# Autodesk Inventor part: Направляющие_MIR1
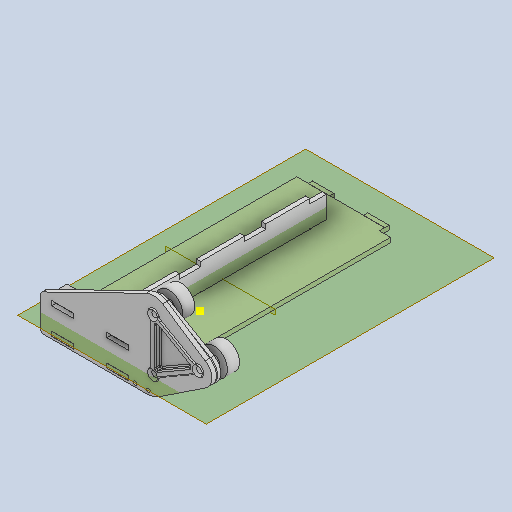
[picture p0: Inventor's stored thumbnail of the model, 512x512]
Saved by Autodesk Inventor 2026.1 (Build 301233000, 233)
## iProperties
Created: 2025-12
Part Number: Направляющие_MIR1
Material: Типовые
Document SubType Name: Modeling
Designer: Yury Melnikov
Density: 1 g/cm^3
Appearance: По умолчанию
Author: Yury Melnikov
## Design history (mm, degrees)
derived "Направляющие.ipt"
  sketch "Эскиз1"
    geometry: L1 (0, 0)-(-16, 0) reference; L2 (-16, 0)-(-16, -200) reference; L3 (-16, -200)-(0, -200) reference; L4 (0, -200)-(0, 0) reference; 1 further point
  sketch "Эскиз2"
    geometry: 1 further point
  sketch "Эскиз3"
    geometry: L1 (0, 0)-(0, -200) reference; L2 (16, -200)-(16, 0) reference; L3 (28.3, -33.725)-(-12.3, -10.284) reference; L4 (-12.3, -10.284)-(-12.3, -57.165) reference; L5 (-12.3, -57.165)-(28.3, -33.725) reference; C1 r 12.3 at (28.3, -33.725) reference; C2 r 12.3 at (-12.3, -10.284) reference; C3 r 12.3 at (-12.3, -57.165) reference; 1 further point
    constraints: 1 other
  sketch "Эскиз4"
    geometry: C1 r 12.3 at (0, 0) reference; C2 r 12.3 at (-40.6, 23.44) reference; C3 r 12.3 at (-40.6, -23.44) reference; C4 r 4 at (0, 0) reference; C5 r 4 at (-40.6, 23.44) reference; C6 r 4 at (-40.6, -23.44) reference; 1 further point
  sketch "Эскиз5"
    geometry: L1 (6.15, 10.652)-(-34.45, 34.093) reference; L2 (-52.9, 23.44)-(-52.9, -23.44) reference; L3 (-34.45, -34.093)-(6.15, -10.652) reference; A1 r 12.3 centre (-40.6, -23.44) between (-34.45, -34.093) and (-52.9, -23.44) reference; A2 r 12.3 centre (-40.6, 23.44) between (-52.9, 23.44) and (-34.45, 34.093) reference; A3 r 12.3 centre (0, 0) between (6.15, -10.652) and (6.15, 10.652) reference; 1 further point
  sketch "Эскиз6"
    geometry: L1 (0, 0)-(-40.6, 23.44) reference; L2 (-40.6, 23.44)-(-40.6, -23.44) reference; L3 (-40.6, -23.44)-(0, 0) reference; L4 (-35.6, 23.44)-(-2.5, 4.33) reference; L5 (-2.5, -4.33)-(-35.6, -23.44) reference; L6 (-43.1, -19.11)-(-43.1, 19.11) reference; L7 (-38.1, 19.11)-(-5, 0) reference; L8 (-5, 0)-(-38.1, -19.11) reference; L9 (-38.1, -19.11)-(-38.1, 19.11) reference; C1 r 12.3 at (-40.6, 23.44) reference; C2 r 12.3 at (-40.6, -23.44) reference; C3 r 12.3 at (0, 0) reference; C4 r 2.5 at (0, 0) reference; C5 r 2.5 at (-40.6, 23.44) reference; C6 r 2.5 at (-40.6, -23.44) reference; A1 r 5 centre (-40.6, 23.44) between (-35.6, 23.44) and (-43.1, 19.11) reference; A2 r 5 centre (0, 0) between (-2.5, -4.33) and (-2.5, 4.33) reference; A3 r 5 centre (-40.6, -23.44) between (-43.1, -19.11) and (-35.6, -23.44) reference; 3 further points
    constraints: 2 other
  sketch "Эскиз7"
    geometry: C1 r 2.5 at (-40.6, 23.44) reference; C2 r 2.5 at (0, 0) reference; C3 r 2.5 at (-40.6, -23.44) reference; 1 further point
  sketch "Эскиз8"
    geometry: L1 (-4.478, 5.472)-(-33.622, 22.298) reference; L2 (-43.1, 16.826)-(-43.1, -16.826) reference; L3 (-33.622, -22.298)-(-4.478, -5.472) reference; L4 (-34.45, 34.093)-(6.15, 10.652) reference; L5 (6.15, -10.652)-(-34.45, -34.093) reference; L6 (-52.9, -23.44)-(-52.9, 23.44) reference; L7 (-30, -82.992)-(-34, -82.992) reference; L8 (-28.3, 33.725)-(-28.3, -166.275) reference; L9 (-142.9, -11.74)-(-142.9, -38.74) reference; L10 (-139.9, -41.74)-(-46.638, -41.74) reference; L11 (-35.571, -38.399)-(6.806, -10.245) reference; L12 (-34.45, 34.093)-(6.15, 10.652) reference; L13 (6.15, 10.652)-(-32.359, 35.974) reference; L14 (-141.217, -9.045)-(-47.187, 36.917) reference; A1 r 5 centre (-1.978, -9.802) between (-0.989, -4.901) and (-4.478, -5.472) reference; A2 r 5 centre (0, 0) between (-0.989, -4.901) and (-0.989, 4.901) reference; A3 r 5 centre (-1.978, 9.802) between (-4.478, 5.472) and (-0.989, 4.901) reference; A4 r 5 centre (-31.122, 26.628) between (-35.861, 25.034) and (-33.622, 22.298) reference; A5 r 5 centre (-40.6, 23.44) between (-35.861, 25.034) and (-44.35, 20.133) reference; A6 r 5 centre (-48.1, 16.826) between (-43.1, 16.826) and (-44.35, 20.133) reference; A7 r 5 centre (-48.1, -16.826) between (-44.35, -20.133) and (-43.1, -16.826) reference; A8 r 5 centre (-40.6, -23.44) between (-44.35, -20.133) and (-35.861, -25.034) reference; A9 r 5 centre (-31.122, -26.628) between (-33.622, -22.298) and (-35.861, -25.034) reference; A10 r 12.3 centre (-40.6, 23.44) between (-34.45, 34.093) and (-52.9, 23.44) reference; A11 r 12.3 centre (0, 0) between (6.15, -10.652) and (6.15, 10.652) reference; A12 r 12.3 centre (-40.6, -23.44) between (-52.9, -23.44) and (-34.45, -34.093) reference; A13 r 12.3 centre (0, 0) between (6.15, -10.652) and (6.15, 10.652) reference; A14 r 12.3 centre (-40.6, 23.44) between (-34.45, 34.093) and (-52.9, 23.44) reference; A15 r 20 centre (-46.638, -21.74) between (-46.638, -41.74) and (-35.571, -38.399) reference; A16 r 3 centre (-139.9, -11.74) between (-141.217, -9.045) and (-142.9, -11.74) reference; A17 r 3 centre (-139.9, -38.74) between (-142.9, -38.74) and (-139.9, -41.74) reference; A18 r 15 centre (-40.6, 23.44) between (-28.3, 14.855) and (-26.541, 18.21) reference; A19 r 15 centre (-40.6, 23.44) between (-32.359, 35.974) and (-47.187, 36.917) reference; 5 further points
  sketch "Эскиз17"
    geometry: L1 (-15.8, 7.674)-(-15.8, 4.326) reference; L2 (-15.8, 4.326)-(-12.9, 2.651) reference; L3 (-12.9, 2.651)-(-10, 4.326) reference; L4 (-10, 4.326)-(-10, 7.674) reference; L5 (-10, 7.674)-(-12.9, 9.349) reference; L6 (-12.9, 9.349)-(-15.8, 7.674) reference; L7 (-12.9, 0.342)-(-17.8, 3.171) reference; L8 (-17.8, 3.171)-(-17.8, 8.829) reference; L9 (-17.8, 8.829)-(-12.9, 11.658) reference; L10 (-12.9, 11.658)-(-8, 8.829) reference; L11 (-8, 8.829)-(-8, 3.171) reference; L12 (-8, 3.171)-(-12.9, 0.342) reference; L13 (0, 0)-(0, 12) reference; L14 (0, 17)-(-89.98, 17) reference; L15 (-29.393, 8.829)-(-29.393, 3.171) reference; L16 (-31.393, 4.326)-(-31.393, 7.674) reference; L17 (-34.293, 2.651)-(-31.393, 4.326) reference; L18 (-34.293, 11.658)-(-29.393, 8.829) reference; L19 (-29.393, 3.171)-(-34.293, 0.342) reference; L20 (-31.393, 7.674)-(-34.293, 9.349) reference; L21 (-37.193, 4.326)-(-34.293, 2.651) reference; L22 (-37.193, 7.674)-(-37.193, 4.326) reference; L23 (-34.293, 9.349)-(-37.193, 7.674) reference; L24 (-34.293, 0.342)-(-39.193, 3.171) reference; L25 (-39.193, 3.171)-(-39.193, 8.829) reference; L26 (-39.193, 8.829)-(-34.293, 11.658) reference; L27 (-50.786, 8.829)-(-50.786, 3.171) reference; L28 (-52.786, 4.326)-(-52.786, 7.674) reference; L29 (-55.686, 2.651)-(-52.786, 4.326) reference; L30 (-55.686, 11.658)-(-50.786, 8.829) reference; L31 (-50.786, 3.171)-(-55.686, 0.342) reference; L32 (-52.786, 7.674)-(-55.686, 9.349) reference; L33 (-58.586, 4.326)-(-55.686, 2.651) reference; L34 (-58.586, 7.674)-(-58.586, 4.326) reference; L35 (-55.686, 9.349)-(-58.586, 7.674) reference; L36 (-55.686, 0.342)-(-60.586, 3.171) reference; L37 (-60.586, 3.171)-(-60.586, 8.829) reference; L38 (-60.586, 8.829)-(-55.686, 11.658) reference; L39 (-72.18, 8.829)-(-72.18, 3.171) reference; L40 (-74.18, 4.326)-(-74.18, 7.674) reference; L41 (-77.08, 2.651)-(-74.18, 4.326) reference; L42 (-77.08, 11.658)-(-72.18, 8.829) reference; L43 (-72.18, 3.171)-(-77.08, 0.342) reference; L44 (-74.18, 7.674)-(-77.08, 9.349) reference; L45 (-79.98, 4.326)-(-77.08, 2.651) reference; L46 (-79.98, 7.674)-(-79.98, 4.326) reference; L47 (-77.08, 9.349)-(-79.98, 7.674) reference; L48 (-77.08, 0.342)-(-81.98, 3.171) reference; L49 (-81.98, 3.171)-(-81.98, 8.829) reference; L50 (-81.98, 8.829)-(-77.08, 11.658) reference; L51 (-89.98, 0)-(-89.98, 12) reference; 11 further points
    constraints: 1 horizontal, 1 other
  sketch "Эскиз18"
    geometry: L1 (-5.8, 3.349)-(-2.9, 5.023) reference; L2 (-2.9, 5.023)-(0, 3.349) reference; L3 (0, 3.349)-(0, 0) reference; L4 (0, 0)-(-2.9, -1.674) reference; L5 (-2.9, -1.674)-(-5.8, 0) reference; L6 (-5.8, 0)-(-5.8, 3.349) reference; L7 (-5.8, 3.349)-(-5.8, 0) reference; L8 (10, 7.674)-(-79.98, 7.674) reference; C1 r 1.65 at (-2.9, 1.674) reference; C2 r 1.65 at (-24.293, 1.674) reference; C3 r 1.65 at (-45.686, 1.674) reference; C4 r 1.65 at (-67.08, 1.674) reference; 3 further points
    constraints: 1 horizontal
  sketch "Эскиз19"
    geometry: L1 (82.72, -35.74)-(82.72, -39.54) reference; L2 (63.12, -35.74)-(82.72, -35.74) reference; L3 (63.12, -39.54)-(63.12, -35.74) reference; L4 (82.72, -39.54)-(63.12, -39.54) reference; L5 (62.92, -11.54)-(82.92, -11.54) reference; L6 (82.92, -11.54)-(82.92, -15.74) reference; L7 (82.92, -15.74)-(62.92, -15.74) reference; L8 (62.92, -15.74)-(62.92, -11.54) reference; L9 (142.9, -15.74)-(52.92, -15.74) reference; L10 (112.9, -11.54)-(132.9, -11.54) reference; L11 (132.9, -11.54)-(132.9, -15.74) reference; L12 (132.9, -15.74)-(112.9, -15.74) reference; L13 (112.9, -15.74)-(112.9, -11.54) reference; L14 (112.9, -39.74)-(112.9, -35.54) reference; L15 (132.9, -35.54)-(132.9, -39.74) reference; L16 (62.92, -39.74)-(62.92, -35.54) reference; L17 (82.92, -35.54)-(82.92, -39.74) reference; 1 further point
  sketch "Эскиз20"
    geometry: L1 (-47.09, -35)-(-42.89, -35) reference; L2 (-42.89, -35)-(-42.89, -75) reference; L3 (-42.89, -75)-(-47.09, -75) reference; L4 (-47.09, -75)-(-47.09, -35) reference; L5 (-47.09, -94)-(-42.89, -94) reference; L6 (-42.89, -94)-(-42.89, -134) reference; L7 (-42.89, -134)-(-47.09, -134) reference; L8 (-47.09, -134)-(-47.09, -94) reference; L9 (-47.09, -153)-(-42.89, -153) reference; L10 (-42.89, -153)-(-42.89, -193) reference; L11 (-42.89, -193)-(-47.09, -193) reference; L12 (-47.09, -193)-(-47.09, -153) reference; L13 (0, -20)-(-89.98, -20) reference; L14 (0, 0)-(-89.98, 0) reference; L15 (-89.98, -228)-(0, -228) reference; 3 further points
    constraints: 1 vertical
  sketch "Эскиз21"
    geometry: L1 (-47.09, -193)-(-42.89, -193) reference; L2 (-42.89, -193)-(-42.89, -153) reference; L3 (-42.89, -153)-(-47.09, -153) reference; L4 (-47.09, -153)-(-47.09, -193) reference; L5 (-47.09, -134)-(-42.89, -134) reference; L6 (-42.89, -134)-(-42.89, -94) reference; L7 (-42.89, -94)-(-47.09, -94) reference; L8 (-47.09, -94)-(-47.09, -134) reference; L9 (-47.09, -75)-(-42.89, -75) reference; L10 (-42.89, -75)-(-42.89, -35) reference; L11 (-42.89, -35)-(-47.09, -35) reference; L12 (-47.09, -35)-(-47.09, -75) reference; L13 (-89.98, 0)-(0, 0) reference; L14 (0, 0)-(0, -228) reference; L15 (-89.98, -228)-(0, -228) reference; L16 (-89.98, 0)-(-89.98, -228) reference; L17 (-46.99, -74.9)-(-42.99, -74.9) reference; L18 (-42.99, -74.9)-(-42.99, -35.1) reference; L19 (-42.99, -35.1)-(-46.99, -35.1) reference; L20 (-46.99, -35.1)-(-46.99, -74.9) reference; L21 (-46.99, -133.9)-(-42.99, -133.9) reference; L22 (-42.99, -133.9)-(-42.99, -94.1) reference; L23 (-42.99, -94.1)-(-46.99, -94.1) reference; L24 (-46.99, -94.1)-(-46.99, -133.9) reference; L25 (-46.99, -192.9)-(-42.99, -192.9) reference; L26 (-42.99, -192.9)-(-42.99, -153.1) reference; L27 (-42.99, -153.1)-(-46.99, -153.1) reference; L28 (-46.99, -153.1)-(-46.99, -192.9) reference; L29 (0, -20)-(-89.98, -20) reference; L30 (-46.99, -20)-(-42.99, -20) reference; L31 (-42.99, -20)-(-42.99, -208) reference; L32 (-42.99, -208)-(-46.99, -208) reference; L33 (-46.99, -208)-(-46.99, -20) reference; C1 r 1.65 at (-55.686, -14) reference; C2 r 1.65 at (-34.293, -14) reference; C3 r 1.65 at (-77.08, -14) reference; C4 r 1.65 at (-12.9, -14) reference; 1 further point
  sketch "Эскиз22"
    geometry: L1 (-46.99, -20)-(-42.99, -20) reference; L2 (-42.99, -20)-(-42.99, -208) reference; L3 (-42.99, -208)-(-46.99, -208) reference; L4 (-46.99, -208)-(-46.99, -20) reference; L5 (0, -20)-(-89.98, -20) reference; L6 (-89.98, -228)-(0, -228) reference; 3 further points
  node "РабПлоскость1"
  node "РабПлоскость2"
  node "РабПлоскость3"
  node "РабПлоскость4"
feature "Твердое тело1::Направляющие.ipt" dims "d0" = 10
feature "Твердое тело2::Направляющие.ipt" dims "d0" = 10
feature "Каретка::Направляющие.ipt" dims "d0" = 10
feature "Рука::Направляющие.ipt" dims "d0" = 10
feature "Основная плита::Направляющие.ipt" dims "d0" = 10
feature "Крепление::Направляющие.ipt" dims "d0" = 10
feature "Ребро жесткости::Направляющие.ipt" dims "d0" = 10
tag "Элемент создания тегов1"
sketch "Эскиз11"
  geometry: L1 (6.806, -10.245)-(-35.571, -38.399) reference; L2 (-46.638, -41.74)-(-139.9, -41.74) reference; L3 (-142.9, -38.74)-(-142.9, -11.74) reference; L4 (-33.622, -22.298)-(-4.478, -5.472) reference; L5 (-4.478, 5.472)-(-33.622, 22.298) reference; L6 (-43.1, 16.826)-(-43.1, -16.826) reference; L7 (-31.268, -35.54)-(-142.9, -35.54) reference; L8 (-37.92, -39.74)-(-142.728, -39.74) reference; L9 (-62.92, -35.54)-(-82.92, -35.54) reference; L10 (-82.92, -35.54)-(-82.92, -39.74) reference; L11 (-82.92, -39.74)-(-62.92, -39.74) reference; L12 (-62.92, -39.74)-(-62.92, -35.54) reference; L13 (-112.9, -35.54)-(-132.9, -35.54) reference; L14 (-132.9, -35.54)-(-132.9, -39.74) reference; L15 (-132.9, -39.74)-(-112.9, -39.74) reference; L16 (-112.9, -39.74)-(-112.9, -35.54) reference; L17 (-32.359, 35.974)-(6.15, 10.652) reference; L18 (-141.217, -9.045)-(-47.187, 36.917) reference; A1 r 12.3 centre (0, 0) between (6.806, -10.245) and (6.15, 10.652) reference; A2 r 20 centre (-46.638, -21.74) between (-46.638, -41.74) and (-35.571, -38.399) reference; A3 r 3 centre (-139.9, -38.74) between (-142.9, -38.74) and (-139.9, -41.74) reference; A4 r 3 centre (-139.9, -11.74) between (-141.217, -9.045) and (-142.9, -11.74) reference; A5 r 5 centre (-1.978, -9.802) between (-0.989, -4.901) and (-4.478, -5.472) reference; A6 r 5 centre (0, 0) between (-0.989, -4.901) and (-0.989, 4.901) reference; A7 r 5 centre (-1.978, 9.802) between (-4.478, 5.472) and (-0.989, 4.901) reference; A8 r 5 centre (-31.122, 26.628) between (-35.861, 25.034) and (-33.622, 22.298) reference; A9 r 5 centre (-40.6, 23.44) between (-35.861, 25.034) and (-44.35, 20.133) reference; A10 r 5 centre (-48.1, 16.826) between (-43.1, 16.826) and (-44.35, 20.133) reference; A11 r 5 centre (-48.1, -16.826) between (-44.35, -20.133) and (-43.1, -16.826) reference; A12 r 5 centre (-40.6, -23.44) between (-44.35, -20.133) and (-35.861, -25.034) reference; A13 r 5 centre (-31.122, -26.628) between (-33.622, -22.298) and (-35.861, -25.034) reference; A14 r 15 centre (-40.6, 23.44) between (-32.359, 35.974) and (-47.187, 36.917) reference; 1 further point
sketch "Эскиз14"
  geometry: L1 (142.9, -35.54)-(52.92, -35.54) reference; L2 (52.92, -35.54)-(52.92, -39.74) reference; L3 (52.92, -39.74)-(142.9, -39.74) reference; L4 (142.9, -39.74)-(142.9, -35.54) reference; L5 (82.92, -35.54)-(62.92, -35.54) reference; L6 (62.92, -39.74)-(82.92, -39.74) reference; L7 (62.92, -35.54)-(62.92, -39.74) reference; L8 (142.9, -38.74)-(142.9, -11.74) reference; 2 further points
sketch "Эскиз15"
  geometry: L1 (-3, 15)-(-3, 11.2) reference; L2 (-3, 11.2)-(-8, 6.2) reference; L3 (-8, 6.2)-(-20, 6.2) reference; L4 (-20, 6.2)-(-20, 3.2) reference; L5 (-20, 3.2)-(0, 3.2) reference; L6 (0, 3.2)-(-228, 3.2) reference; L7 (0, 3.2)-(0, 23) reference; L8 (0, 23)-(-20, 23) reference; L9 (-3, 15)-(-8, 20) reference; L10 (-8, 20)-(-20, 20) reference; L11 (-20, 20)-(-20, 23) reference; 5 further points; 1 other entity
  constraints: 1 other
sketch "Эскиз16"
  geometry: L1 (-52.92, -35.54)-(-142.9, -35.54) reference; L2 (-52.92, -39.74)-(-52.92, -35.54) reference; L3 (-142.9, -39.74)-(-52.92, -39.74) reference; L4 (-142.9, -35.54)-(-142.9, -39.74) reference; L5 (-132.9, -35.54)-(-132.9, -39.74) reference; L6 (-132.9, -39.74)-(-112.9, -39.74) reference; L7 (-112.9, -39.74)-(-112.9, -35.54) reference; L8 (-112.9, -35.54)-(-132.9, -35.54) reference; L9 (-82.92, -35.54)-(-82.92, -39.74) reference; L10 (-82.92, -39.74)-(-62.92, -39.74) reference; L11 (-62.92, -39.74)-(-62.92, -35.54) reference; L12 (-62.92, -35.54)-(-82.92, -35.54) reference; L13 (6.806, -10.245)-(-35.571, -38.399) reference; L14 (-46.638, -41.74)-(-139.9, -41.74) reference; L15 (-142.9, -38.74)-(-142.9, -11.74) reference; L16 (-141.217, -9.045)-(-47.187, 36.917) reference; L17 (-32.359, 35.974)-(6.15, 10.652) reference; L18 (-33.622, -22.298)-(-4.478, -5.472) reference; L19 (-4.478, 5.472)-(-33.622, 22.298) reference; L20 (-43.1, 16.826)-(-43.1, -16.826) reference; L21 (-82.72, -39.54)-(-82.72, -35.74) reference; L22 (-82.72, -35.74)-(-63.12, -35.74) reference; L23 (-63.12, -35.74)-(-63.12, -39.54) reference; L24 (-63.12, -39.54)-(-82.72, -39.54) reference; L25 (-113.1, -35.74)-(-113.1, -39.54) reference; L26 (-113.1, -39.54)-(-132.7, -39.54) reference; L27 (-132.7, -39.54)-(-132.7, -35.74) reference; L28 (-132.7, -35.74)-(-113.1, -35.74) reference; A1 r 12.3 centre (0, 0) between (6.806, -10.245) and (6.15, 10.652) reference; A2 r 20 centre (-46.638, -21.74) between (-46.638, -41.74) and (-35.571, -38.399) reference; A3 r 3 centre (-139.9, -38.74) between (-142.9, -38.74) and (-139.9, -41.74) reference; A4 r 3 centre (-139.9, -11.74) between (-141.217, -9.045) and (-142.9, -11.74) reference; A5 r 15 centre (-40.6, 23.44) between (-32.359, 35.974) and (-47.187, 36.917) reference; A6 r 5 centre (-1.978, -9.802) between (-0.989, -4.901) and (-4.478, -5.472) reference; A7 r 5 centre (0, 0) between (-0.989, -4.901) and (-0.989, 4.901) reference; A8 r 5 centre (-1.978, 9.802) between (-4.478, 5.472) and (-0.989, 4.901) reference; A9 r 5 centre (-31.122, 26.628) between (-35.861, 25.034) and (-33.622, 22.298) reference; A10 r 5 centre (-40.6, 23.44) between (-35.861, 25.034) and (-44.35, 20.133) reference; A11 r 5 centre (-48.1, 16.826) between (-43.1, 16.826) and (-44.35, 20.133) reference; A12 r 5 centre (-48.1, -16.826) between (-44.35, -20.133) and (-43.1, -16.826) reference; A13 r 5 centre (-40.6, -23.44) between (-44.35, -20.133) and (-35.861, -25.034) reference; A14 r 5 centre (-31.122, -26.628) between (-33.622, -22.298) and (-35.861, -25.034) reference; 1 further point
node "Твердое тело1"
node "Твердое тело2"
node "Каретка"
node "Рука"
node "Основная плита"
node "Крепление"
node "Ребро жесткости"
